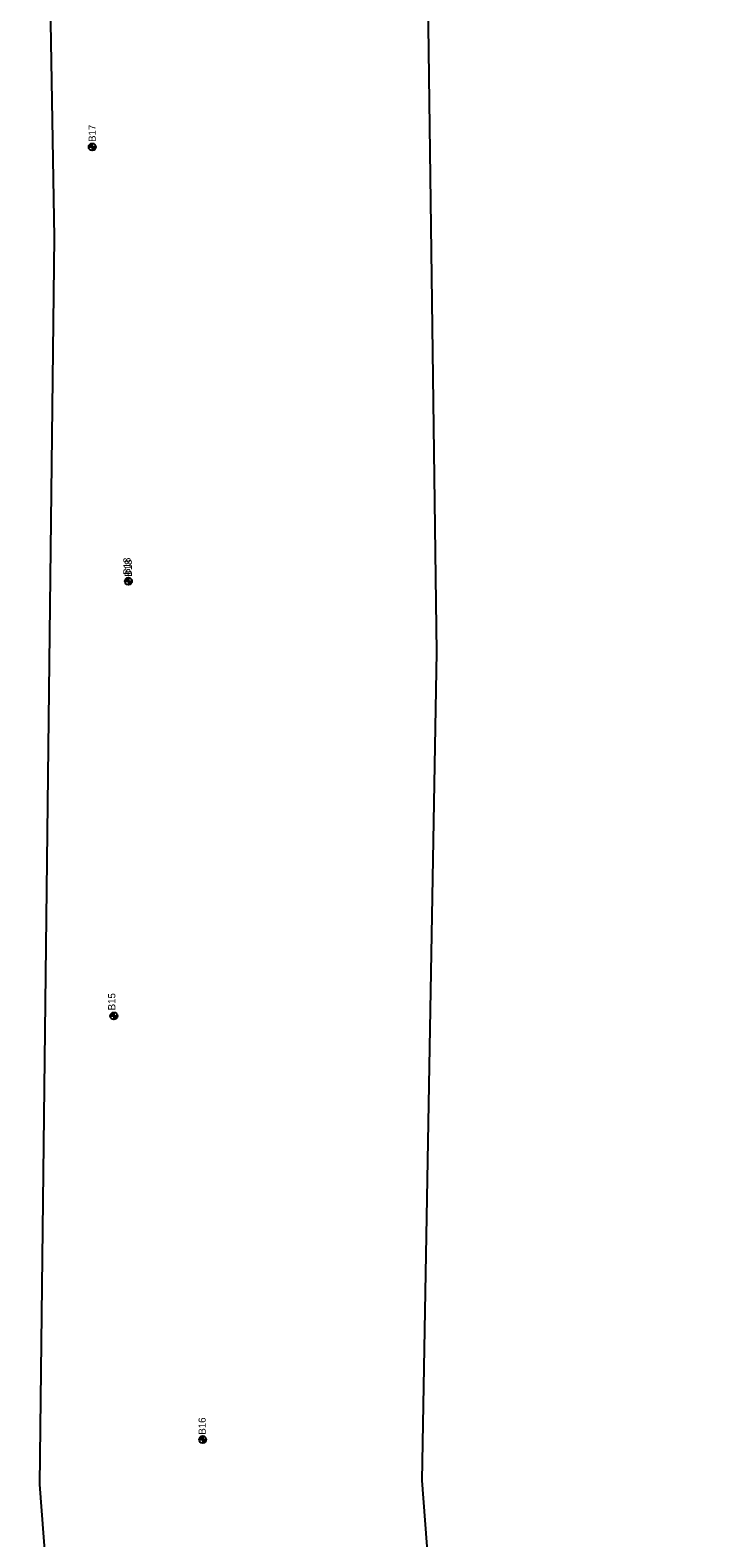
# Model space of a CAD drawing. Extents: x 335726 to 369746, y 119154 to 200788.
# Drawn here: x 361057 to 361992, y 136037 to 138131 of the extents above; entities that cross this region are included whole.
import ezdxf

# ---------------------------------------------------------------- set-up
doc = ezdxf.new("R2010")
doc.units = 0
for name, color, linetype in [('E_SOIL_BORE1 [KAPUR_CADDS_LEVELS]', 7, 'Continuous'), ('E_SOIL_BORE2 [KAPUR_CADDS_LEVELS]', 7, 'Continuous'), ('P_MARK', 7, 'Continuous'), ('P_TC', 7, 'Continuous')]:
    doc.layers.add(name, color=color, linetype=linetype)

msp = doc.modelspace()

# ---------------------------------------------------------------- linework, layer by layer
at = {"layer": 'P_MARK'}
for p, q in [((361138.1, 137968.3), (361148.1, 137968.3)), ((361143.1, 137973.3), (361143.1, 137963.3)), ((361193.2, 137370.2), (361193.2, 137360.2)), ((361188.2, 137365.2), (361198.2, 137365.2)), ((361168.1, 136761.5), (361178.1, 136761.5)), ((361173.1, 136766.5), (361173.1, 136756.5)), ((361296.4, 136178.3), (361296.4, 136168.3)), ((361291.4, 136173.3), (361301.4, 136173.3))]:
    msp.add_line(p, q, dxfattribs=at)
for centre in [(361143.1, 137968.3), (361193.2, 137365.2), (361173.1, 136761.5), (361296.4, 136173.3)]:
    msp.add_circle(centre, 5, dxfattribs=at)
for centre, radius, start, end in [((361143.1, 137968.3), 4.5, 89.9869, 179.9869), ((361143.1, 137968.3), 4, 89.9869, 179.9869), ((361143.1, 137968.3), 3.5, 89.9869, 179.9869), ((361143.1, 137968.3), 3, 89.9869, 179.9869), ((361143.1, 137968.3), 2.5, 89.9869, 179.9869), ((361143.1, 137968.3), 2, 89.9869, 179.9869), ((361143.1, 137968.3), 1.5, 89.9869, 179.9869), ((361143.1, 137968.3), 1, 89.9869, 179.9869), ((361143.1, 137968.3), 0.5, 89.9869, 179.9869), ((361143.1, 137968.3), 4.5, 269.9869, 359.9869), ((361143.1, 137968.3), 4, 269.9869, 359.9869), ((361143.1, 137968.3), 3.5, 269.9869, 359.9869), ((361143.1, 137968.3), 3, 269.9869, 359.9869), ((361143.1, 137968.3), 2.5, 269.9869, 359.9869), ((361143.1, 137968.3), 2, 269.9869, 359.9869), ((361143.1, 137968.3), 1.5, 269.9869, 359.9869), ((361143.1, 137968.3), 1, 269.9869, 359.9869), ((361143.1, 137968.3), 0.5, 269.9869, 359.9869), ((361193.2, 137365.2), 4.5, 89.9869, 179.9869), ((361193.2, 137365.2), 4, 89.9869, 179.9869), ((361193.2, 137365.2), 3.5, 89.9869, 179.9869), ((361193.2, 137365.2), 3, 89.9869, 179.9869), ((361193.2, 137365.2), 2.5, 89.9869, 179.9869), ((361193.2, 137365.2), 2, 89.9869, 179.9869), ((361193.2, 137365.2), 1.5, 89.9869, 179.9869), ((361193.2, 137365.2), 1, 89.9869, 179.9869), ((361193.2, 137365.2), 0.5, 89.9869, 179.9869), ((361193.2, 137365.2), 4.5, 269.9869, 359.9869), ((361193.2, 137365.2), 4, 269.9869, 359.9869), ((361193.2, 137365.2), 3.5, 269.9869, 359.9869), ((361193.2, 137365.2), 3, 269.9869, 359.9869), ((361193.2, 137365.2), 2.5, 269.9869, 359.9869), ((361193.2, 137365.2), 2, 269.9869, 359.9869), ((361193.2, 137365.2), 1.5, 269.9869, 359.9869), ((361193.2, 137365.2), 1, 269.9869, 359.9869), ((361193.2, 137365.2), 0.5, 269.9869, 359.9869), ((361173.1, 136761.5), 4.5, 89.9869, 179.9869), ((361173.1, 136761.5), 4, 89.9869, 179.9869), ((361173.1, 136761.5), 3.5, 89.9869, 179.9869), ((361173.1, 136761.5), 3, 89.9869, 179.9869), ((361173.1, 136761.5), 2.5, 89.9869, 179.9869), ((361173.1, 136761.5), 2, 89.9869, 179.9869), ((361173.1, 136761.5), 1.5, 89.9869, 179.9869), ((361173.1, 136761.5), 1, 89.9869, 179.9869), ((361173.1, 136761.5), 0.5, 89.9869, 179.9869), ((361173.1, 136761.5), 4.5, 269.9869, 359.9869), ((361173.1, 136761.5), 4, 269.9869, 359.9869), ((361173.1, 136761.5), 3.5, 269.9869, 359.9869), ((361173.1, 136761.5), 3, 269.9869, 359.9869), ((361173.1, 136761.5), 2.5, 269.9869, 359.9869), ((361173.1, 136761.5), 2, 269.9869, 359.9869), ((361173.1, 136761.5), 1.5, 269.9869, 359.9869), ((361173.1, 136761.5), 1, 269.9869, 359.9869), ((361173.1, 136761.5), 0.5, 269.9869, 359.9869), ((361296.4, 136173.3), 4.5, 89.9869, 179.9869), ((361296.4, 136173.3), 4, 89.9869, 179.9869), ((361296.4, 136173.3), 3.5, 89.9869, 179.9869), ((361296.4, 136173.3), 3, 89.9869, 179.9869), ((361296.4, 136173.3), 2.5, 89.9869, 179.9869), ((361296.4, 136173.3), 2, 89.9869, 179.9869), ((361296.4, 136173.3), 1.5, 89.9869, 179.9869), ((361296.4, 136173.3), 1, 89.9869, 179.9869), ((361296.4, 136173.3), 0.5, 89.9869, 179.9869), ((361296.4, 136173.3), 4.5, 269.9869, 359.9869), ((361296.4, 136173.3), 4, 269.9869, 359.9869), ((361296.4, 136173.3), 3.5, 269.9869, 359.9869), ((361296.4, 136173.3), 3, 269.9869, 359.9869), ((361296.4, 136173.3), 2.5, 269.9869, 359.9869), ((361296.4, 136173.3), 2, 269.9869, 359.9869), ((361296.4, 136173.3), 1.5, 269.9869, 359.9869), ((361296.4, 136173.3), 1, 269.9869, 359.9869), ((361296.4, 136173.3), 0.5, 269.9869, 359.9869)]:
    msp.add_arc(centre, radius, start, end, dxfattribs=at)
at = {"layer": 'P_TC'}
for points in [[(361210.6, 132771.7), (361223.4, 134674), (361108.2, 135610.9), (361070.4, 136110.7), (361090.7, 137842.8), (361056.9, 139823.2), (361093.9, 140191), (361349.1, 141419.1), (361464, 142426.1)], [(361992.3, 142388.8), (361875.2, 141362.7), (361620.5, 140136.7), (361587.1, 139805.4), (361621.2, 137266.8), (361600.6, 136116.2), (361636.6, 135639.5), (361753.9, 134686.1), (361737.7, 134039), (361751.8, 132291.5)]]:
    msp.add_lwpolyline(points, dxfattribs=at)

# ---------------------------------------------------------------- texts
at = {"layer": 'E_SOIL_BORE1 [KAPUR_CADDS_LEVELS]'}
for s, p in [('B17', (361147.9, 137975.3)), ('B18', (361196.2, 137374.2))]:
    msp.add_text(s, height=10, rotation=89.9869, dxfattribs=at).set_placement(p)
at = {"layer": 'E_SOIL_BORE2 [KAPUR_CADDS_LEVELS]'}
for s, p in [('B18', (361198.1, 137371.6)), ('B15', (361175.1, 136769.4)), ('B16', (361300.6, 136180.1))]:
    msp.add_text(s, height=10, rotation=89.9869, dxfattribs=at).set_placement(p)

doc.saveas('drawing.dxf')
